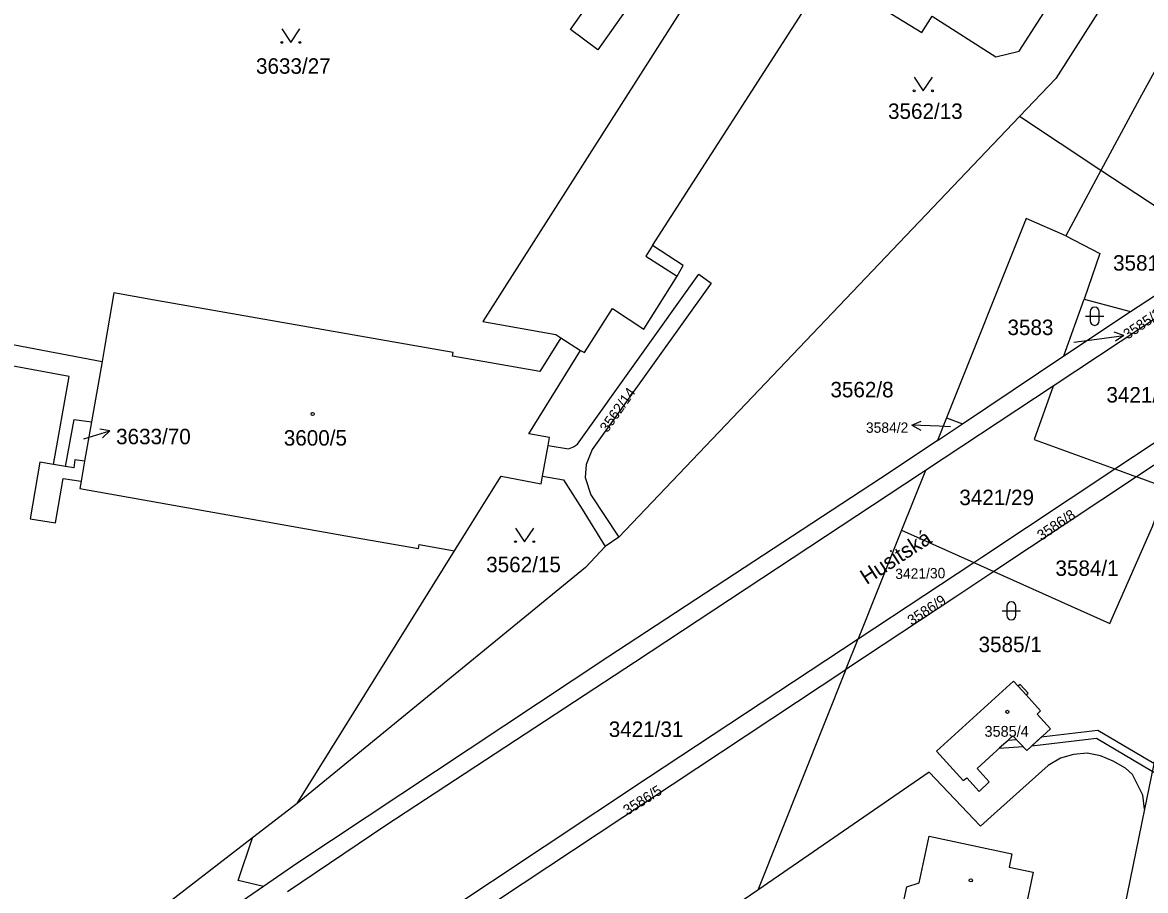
# Model space of a CAD drawing. Extents: x -869103 to -863415, y -1015889 to -1012477.
# Drawn here: x -867343.5 to -867219.9, y -1014509.2 to -1014413.7 of the extents above; entities that cross this region are included whole.
import ezdxf

# ---------------------------------------------------------------- set-up
doc = ezdxf.new("R2010")
doc.units = 0
for name, color, linetype in [('Hranice parcel', 7, 'Continuous'), ('Parcelní čísla', 7, 'Continuous'), ('Pop  PČ popisy', 7, 'Continuous'), ('Vnitřní kresba', 7, 'Continuous'), ('Věcná břemena k části', 7, 'Continuous'), ('Značky budov', 7, 'Continuous'), ('Značky kultur', 7, 'Continuous')]:
    doc.layers.add(name, color=color, linetype=linetype)

msp = doc.modelspace()

# ---------------------------------------------------------------- linework, layer by layer
at = {"layer": 'Hranice parcel'}
for p, q in [((-867210.72, -1014404.2), (-867220.53, -1014422.07)), ((-867220.53, -1014422.07), (-867224.77, -1014429.96)), ((-867233.75, -1014424.03), (-867277.84, -1014470.32)), ((-867224.77, -1014429.96), (-867233.75, -1014424.03)), ((-867224.77, -1014429.96), (-867228.64, -1014437.17)), ((-867211.35, -1014438.82), (-867224.77, -1014429.96)), ((-867221.51, -1014445.47), (-867211.35, -1014438.82)), ((-867228.85, -1014450.37), (-867226.62, -1014444.13)), ((-867226.62, -1014444.13), (-867221.51, -1014445.47)), ((-867217.66, -1014445.52), (-867230.04, -1014453.69)), ((-867228.85, -1014450.37), (-867221.51, -1014445.47)), ((-867284.22, -1014448.37), (-867282.05, -1014449.77)), ((-867240.03, -1014457.84), (-867228.85, -1014450.37)), ((-867334.73, -1014450.96), (-867335.9, -1014457.62)), ((-867230.04, -1014453.69), (-867244.09, -1014462.97)), ((-867223.25, -1014462.8), (-867210.44, -1014454.29)), ((-867241.77, -1014457.18), (-867242.77, -1014459.67)), ((-867242.77, -1014459.67), (-867240.03, -1014457.84)), ((-867241.77, -1014457.18), (-867240.03, -1014457.84)), ((-867211.03, -1014457.16), (-867220.86, -1014463.67)), ((-867286.24, -1014463.59), (-867285.63, -1014460.2)), ((-867242.77, -1014459.67), (-867247.97, -1014463.14)), ((-867338.75, -1014462.53), (-867340.07, -1014462.31)), ((-867244.09, -1014462.97), (-867246.72, -1014469.54)), ((-867244.09, -1014462.97), (-867244.62, -1014463.32)), ((-867223.25, -1014462.8), (-867220.86, -1014463.67)), ((-867220.86, -1014463.67), (-867236.57, -1014474.08)), ((-867277.84, -1014470.32), (-867279.33, -1014471.33)), ((-867246.72, -1014469.54), (-867251.5, -1014481.5)), ((-867246.72, -1014469.54), (-867238.76, -1014473.1)), ((-867313.24, -1014499.62), (-867295.92, -1014471.79)), ((-867251.5, -1014481.5), (-867238.76, -1014473.1)), ((-867236.57, -1014474.08), (-867240.64, -1014476.78)), ((-867238.76, -1014473.1), (-867236.57, -1014474.08)), ((-867240.64, -1014476.78), (-867252.84, -1014484.85)), ((-867274.59, -1014496.71), (-867251.5, -1014481.5)), ((-867252.84, -1014484.85), (-867251.5, -1014481.5)), ((-867296.06, -1014513.44), (-867252.84, -1014484.85)), ((-867252.84, -1014484.85), (-867262.55, -1014509.12)), ((-867298.87, -1014512.81), (-867274.59, -1014496.71)), ((-867313.24, -1014499.62), (-867318.15, -1014503.39)), ((-867318.15, -1014503.39), (-867332.14, -1014514.15)), ((-867313.29, -1014506.2), (-867316.96, -1014508.72)), ((-867316.96, -1014508.72), (-867326.76, -1014515.45))]:
    msp.add_line(p, q, dxfattribs=at)
for points in [[(-867269.2, -1014406.77), (-867272.47, -1014411.84), (-867274.46, -1014411.45), (-867275.47, -1014411.46), (-867276.43, -1014411.79), (-867277.16, -1014412.42), (-867280.15, -1014416.69), (-867283.15, -1014414.45), (-867280.26, -1014410.33), (-867280.05, -1014409.6), (-867280.07, -1014408.64), (-867280.97, -1014406.98), (-867281.42, -1014406.48), (-867299.17, -1014395.45), (-867329.36, -1014376.56), (-867332.82, -1014374.49), (-867334.69, -1014373.73), (-867336.67, -1014373.36), (-867337.69, -1014373.41), (-867338.5, -1014373.95), (-867339.02, -1014374.77), (-867353.21, -1014430.59)], [(-867209.07, -1014384.76), (-867211.63, -1014388.85), (-867222.68, -1014408.77), (-867229.74, -1014419.83), (-867233.75, -1014424.03)], [(-867269.2, -1014406.77), (-867267.98, -1014407.59), (-867292.82, -1014446.56), (-867284.79, -1014448.01), (-867284.22, -1014448.37)], [(-867251.09, -1014410.73), (-867244.49, -1014414.8), (-867243.34, -1014412.99), (-867236.34, -1014417.45), (-867233.76, -1014416.82), (-867227.1, -1014406.43)], [(-867282.05, -1014449.77), (-867281.63, -1014449.97), (-867278.55, -1014445.14), (-867275.1, -1014447.41), (-867271.43, -1014441.59), (-867270.75, -1014440.42), (-867274.14, -1014438.23), (-867256.72, -1014411.1)], [(-867228.64, -1014437.17), (-867233, -1014435.24), (-867241.77, -1014457.18)], [(-867228.64, -1014437.17), (-867224.91, -1014439.09), (-867226.62, -1014444.13)], [(-867285.63, -1014460.2), (-867283.39, -1014460.59), (-867282.83, -1014460.37), (-867282.4, -1014460.08), (-867269.05, -1014441.36), (-867267.69, -1014442.35), (-867280.76, -1014460.67), (-867281.42, -1014462.31), (-867281.53, -1014463.74), (-867280.93, -1014465.66), (-867277.84, -1014470.32)], [(-867284.22, -1014448.37), (-867286.54, -1014452.07), (-867296.16, -1014450.4), (-867296.08, -1014449.97), (-867299.25, -1014449.42), (-867328.95, -1014444.22), (-867333.42, -1014443.44), (-867334.43, -1014449.21), (-867334.73, -1014450.96)], [(-867350.39, -1014448.02), (-867334.73, -1014450.96)], [(-867340.07, -1014462.31), (-867338.35, -1014452.63), (-867350.84, -1014450.32), (-867356, -1014449.49), (-867357.01, -1014449.51), (-867357.87, -1014449.98), (-867358.27, -1014450.52), (-867361.57, -1014463.54), (-867361.76, -1014464.56), (-867361.62, -1014465.34)], [(-867285.63, -1014460.2), (-867285.48, -1014459.35), (-867287.76, -1014458.93), (-867282.53, -1014450.54), (-867282.05, -1014449.77)], [(-867230.04, -1014453.69), (-867232.14, -1014459.57), (-867223.25, -1014462.8)], [(-867338.75, -1014462.53), (-867337.81, -1014457.34), (-867335.9, -1014457.62)], [(-867335.9, -1014457.62), (-867336.65, -1014461.95), (-867337.71, -1014461.79), (-867337.85, -1014462.67), (-867338.75, -1014462.53)], [(-867211.03, -1014457.16), (-867216.75, -1014484.58), (-867219.98, -1014500.23)], [(-867340.07, -1014462.31), (-867341.58, -1014462.07), (-867342.63, -1014468.27), (-867339.84, -1014468.72), (-867338.99, -1014463.85), (-867337.04, -1014464.16), (-867337.18, -1014464.96), (-867306.86, -1014470.33), (-867299.9, -1014471.56), (-867299.82, -1014471.11), (-867295.92, -1014471.79)], [(-867238.76, -1014473.1), (-867237.88, -1014472.52), (-867223.25, -1014462.8)], [(-867244.62, -1014463.32), (-867276.12, -1014484.08), (-867303.48, -1014502.04), (-867314.32, -1014509.32)], [(-867247.97, -1014463.14), (-867279.06, -1014483.52), (-867313.29, -1014506.2)], [(-867295.92, -1014471.79), (-867291.86, -1014465.29), (-867290.81, -1014463.61), (-867286.39, -1014464.43), (-867286.24, -1014463.59)], [(-867286.24, -1014463.59), (-867283.95, -1014464.01), (-867281.87, -1014467.24), (-867279.33, -1014471.33)], [(-867236.57, -1014474.08), (-867223.81, -1014479.8), (-867219.09, -1014469.13), (-867217.59, -1014464.86), (-867220.86, -1014463.67)], [(-867279.33, -1014471.33), (-867281.51, -1014473.65), (-867313.24, -1014499.62)], [(-867238.18, -1014498.27), (-867237.06, -1014497.22), (-867238.39, -1014495.75), (-867234.47, -1014492.17), (-867232.93, -1014493.76), (-867230.33, -1014491.39), (-867231.81, -1014489.79), (-867231.42, -1014489.4), (-867233, -1014487.66), (-867232.78, -1014487.46), (-867233.66, -1014486.5), (-867233.88, -1014486.7), (-867234.38, -1014486.15), (-867242.89, -1014493.84), (-867239.95, -1014497.07), (-867239.55, -1014496.78), (-867238.18, -1014498.27)], [(-867219.98, -1014500.23), (-867220.16, -1014498.7), (-867221.31, -1014496.41), (-867222.06, -1014495.71), (-867223.41, -1014494.95), (-867224.81, -1014494.35), (-867226.28, -1014494.08), (-867227.81, -1014494.2), (-867229.24, -1014494.61), (-867230.59, -1014495.42), (-867236.53, -1014500.74), (-867238.02, -1014502.08), (-867243.67, -1014496.16), (-867262.55, -1014509.12)], [(-867219.98, -1014500.23), (-867225.4, -1014526.73), (-867226.37, -1014526.59)], [(-867316.96, -1014508.72), (-867319.75, -1014508.09), (-867318.15, -1014503.39)], [(-867234.89, -1014506.6), (-867232.22, -1014507.15), (-867234.74, -1014518.93), (-867241.61, -1014517.45), (-867240.79, -1014513.58), (-867245.68, -1014512.49), (-867246.73, -1014511.5), (-867246.15, -1014508.77), (-867244.8, -1014508.33), (-867243.67, -1014503.2), (-867234.58, -1014505.13), (-867234.89, -1014506.6)], [(-867262.55, -1014509.12), (-867271.05, -1014514.95), (-867271.7, -1014520.15)]]:
    msp.add_lwpolyline(points, dxfattribs=at)
at = {"layer": 'Pop  PČ popisy'}
for p, q in [((-867225.23, -1014448.52), (-867222.26, -1014448.1)), ((-867222.26, -1014448.1), (-867223.32, -1014447.75)), ((-867222.26, -1014448.1), (-867223.18, -1014448.74)), ((-867227.74, -1014448.85), (-867225.23, -1014448.52)), ((-867245.58, -1014457.99), (-867244.56, -1014457.53)), ((-867242.58, -1014458.1), (-867245.58, -1014457.99)), ((-867245.58, -1014457.99), (-867244.6, -1014458.53)), ((-867241.32, -1014458.15), (-867242.58, -1014458.1)), ((-867336.73, -1014459.47), (-867333.86, -1014458.59)), ((-867333.86, -1014458.59), (-867334.96, -1014458.41)), ((-867333.86, -1014458.59), (-867334.67, -1014459.36))]:
    msp.add_line(p, q, dxfattribs=at)
at = {"layer": 'Vnitřní kresba'}
for p, q in [((-867274.14, -1014438.23), (-867274.88, -1014439.39)), ((-867274.88, -1014439.39), (-867271.43, -1014441.59)), ((-867336.65, -1014461.95), (-867337.04, -1014464.16)), ((-867233.88, -1014486.7), (-867233, -1014487.66))]:
    msp.add_line(p, q, dxfattribs=at)
at = {"layer": 'Věcná břemena k části'}
for points in [[(-867235.96, -1014493.53), (-867233.34, -1014493.34), (-867234.07, -1014492.59), (-867235, -1014492.66)], [(-867232.37, -1014493.25), (-867225.28, -1014492.42), (-867219.12, -1014496.04), (-867213.66, -1014499.24), (-867213.91, -1014500.46), (-867213.72, -1014501.48), (-867213.54, -1014501.49), (-867213.06, -1014498.67), (-867218.94, -1014495.21), (-867225.11, -1014491.59), (-867231.35, -1014492.32)]]:
    msp.add_lwpolyline(points, close=True, dxfattribs=at)
at = {"layer": 'Značky budov'}
for centre in [(-867311.55, -1014456.75), (-867235.07, -1014489.52), (-867239.1, -1014508.06)]:
    msp.add_circle(centre, 0.175, dxfattribs=at)
at = {"layer": 'Značky kultur'}
for p, q in [((-867225.96, -1014445.5), (-867225.96, -1014446.5)), ((-867224.96, -1014446.5), (-867224.96, -1014445.5)), ((-867226.46, -1014446), (-867224.46, -1014446)), ((-867235.63, -1014478.4), (-867233.63, -1014478.4)), ((-867235.13, -1014477.9), (-867235.13, -1014478.9)), ((-867234.13, -1014478.9), (-867234.13, -1014477.9))]:
    msp.add_line(p, q, dxfattribs=at)
for points in [[(-867314.95, -1014414.37), (-867313.95, -1014415.87), (-867312.95, -1014414.37)], [(-867245.33, -1014419.7), (-867244.33, -1014421.2), (-867243.33, -1014419.7)], [(-867289.21, -1014469.3), (-867288.21, -1014470.8), (-867287.21, -1014469.3)]]:
    msp.add_lwpolyline(points, dxfattribs=at)
for centre in [(-867314.95, -1014415.87), (-867312.95, -1014415.87), (-867245.33, -1014421.2), (-867243.33, -1014421.2), (-867289.21, -1014470.8), (-867287.21, -1014470.8)]:
    msp.add_circle(centre, 0.1, dxfattribs=at)
for centre, start, end in [((-867225.46, -1014445.5), 0, 180), ((-867225.46, -1014446.5), 180, 359.9879), ((-867234.63, -1014477.9), 0, 180), ((-867234.63, -1014478.9), 180, 359.9879)]:
    msp.add_arc(centre, 0.5, start, end, dxfattribs=at)

# ---------------------------------------------------------------- texts
at = {"layer": 'Parcelní čísla'}
for s, height, p in [('3633/27', 1.7, (-867317.78, -1014419.32)), ('3562/13', 1.7, (-867248.21, -1014424.29)), ('3581/2', 1.7, (-867223.44, -1014440.98)), ('3583', 1.7, (-867235.06, -1014448.07)), ('3562/8', 1.7, (-867254.55, -1014454.92)), ('3421/28', 1.7, (-867224.17, -1014455.49)), ('3584/2', 1.139, (-867250.64, -1014458.82)), ('3633/70', 1.7, (-867333.18, -1014460.08)), ('3600/5', 1.7, (-867314.72, -1014460.23)), ('3421/29', 1.7, (-867240.36, -1014466.78)), ('3562/15', 1.7, (-867292.44, -1014474.16)), ('3584/1', 1.7, (-867229.78, -1014474.56)), ('3585/1', 1.7, (-867238.24, -1014482.95)), ('3421/31', 1.7, (-867278.95, -1014492.28)), ('3585/4', 1.19, (-867237.59, -1014492.26))]:
    msp.add_text(s, height=height, dxfattribs=at).set_placement(p)
for s, rotation, p in [('3585/2', 34, (-867221.83, -1014448.59)), ('3562/14', 55, (-867279.1, -1014458.87)), ('3586/8', 34, (-867231.32, -1014470.72)), ('3421/30', 1, (-867247.4, -1014474.91)), ('3586/9', 33, (-867245.61, -1014480.07)), ('3586/5', 32, (-867276.92, -1014500.95))]:
    msp.add_text(s, height=1.139, rotation=rotation, dxfattribs=at).set_placement(p)
at = {"layer": 'Pop  PČ popisy'}
msp.add_text('Husitská', height=1.7, rotation=33, dxfattribs=at).set_placement((-867250.57, -1014475.58))

doc.saveas('drawing.dxf')
